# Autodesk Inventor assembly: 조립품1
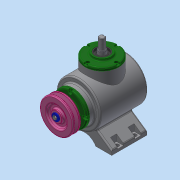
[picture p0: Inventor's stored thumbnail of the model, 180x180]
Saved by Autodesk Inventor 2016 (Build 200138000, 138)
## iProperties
Created: 2021-04
Part Number: 조립품1
Document SubType Name: Assembly
Designer: User
Author: User
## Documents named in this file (16)
- C:\Users\User\Desktop\710407V1008 (1)\조립품1.iam
- C:\Users\User\Desktop\710407V1008 (1)\본체.ipt
- C:\Users\User\Desktop\710407V1008 (1)\서브 축.ipt
- 서브 축.ipt
- C:\Users\User\Desktop\710407V1008 (1)\베어링 6203.ipt
- C:\Users\User\Desktop\710407V1008 (1)\메인 축.ipt
- 메인 축.ipt
- C:\Users\User\Desktop\710407V1008 (1)\커버.ipt
- C:\Users\User\Desktop\710407V1008 (1)\키 4 x 4 x 14.ipt
- C:\Users\User\Desktop\710407V1008 (1)\키 5 x 5 x 14.ipt
- C:\Users\User\Desktop\710407V1008 (1)\서브 베벨기어.ipt
- C:\Users\User\Desktop\710407V1008 (1)\메인 베벨기어.ipt
- C:\Users\User\Desktop\710407V1008 (1)\V-벨트풀리.ipt
- C:\Users\User\Desktop\710407V1008 (1)\와셔 4 x 16.ipt
- C:\Users\User\Desktop\710407V1008 (1)\육각볼트 M4 x 8.ipt
- C:\Users\User\Desktop\710407V1008 (1)\오일실 17 x 32 x 8.ipt
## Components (1 placed, 1 different names)
1. V-벨트풀리:1 — 각도:5
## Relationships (1: Angle 1)
- 각도:5 [Angle]: V-벨트풀리:1
